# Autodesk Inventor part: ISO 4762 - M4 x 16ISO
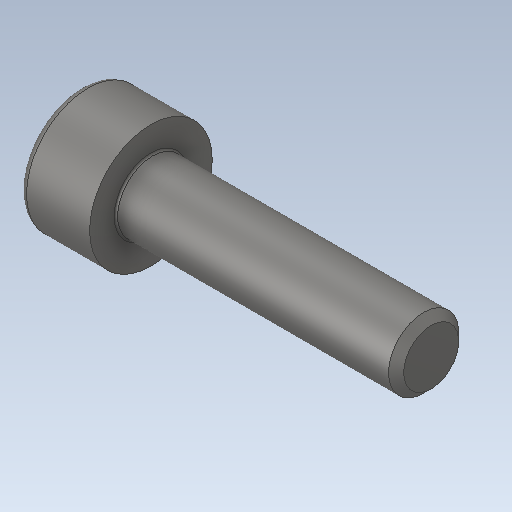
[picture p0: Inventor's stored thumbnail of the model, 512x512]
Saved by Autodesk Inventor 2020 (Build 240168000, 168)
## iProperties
Created: 2015-11
Part Number: ISO 4762 - M4 x 16ISO
Material: Ogólny
Document SubType Name: Modeling
Designer: Tomasz
Density: 1 g/cm^3
Appearance: Domyślna
Sending System: SolidWorks 2017
Last Author: Tomasz
Last Saved: 2017-10-01
Author: Tomasz
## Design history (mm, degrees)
feature "Imported1"
node "Bryła1"
